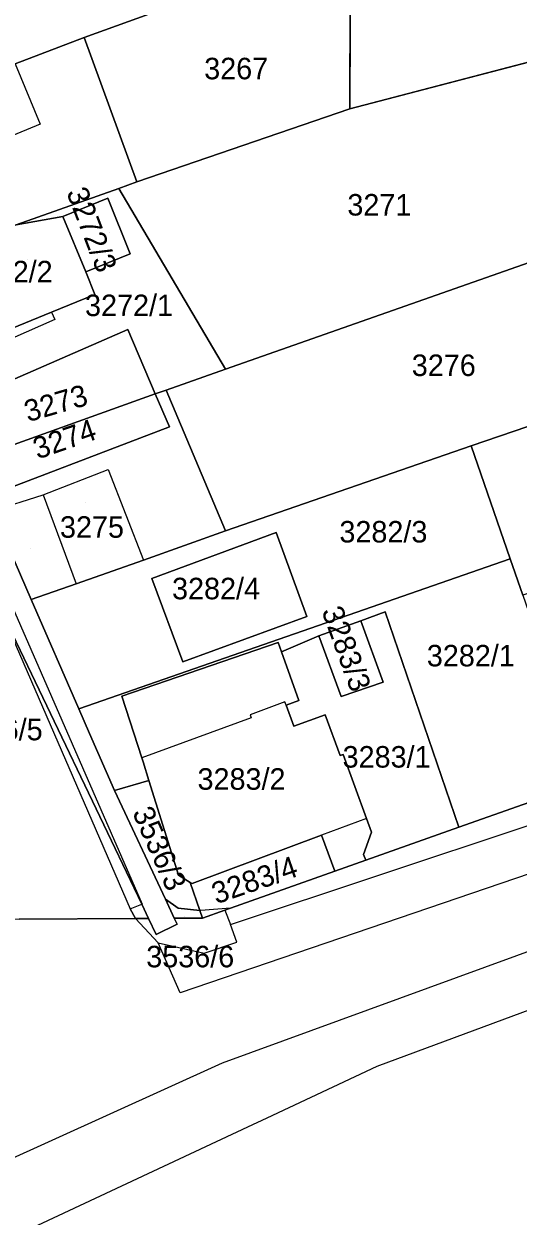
# Model space of a CAD drawing. Extents: x -262657 to -261595, y -1238015 to -1237156.
# Drawn here: x -261855.5 to -261809.5, y -1237959.1 to -1237848.2 of the extents above; entities that cross this region are included whole.
import ezdxf

# ---------------------------------------------------------------- set-up
doc = ezdxf.new("R2010")
doc.units = 0
for name, color, linetype in [('body_kn', 7, 'Continuous'), ('kladpar_druhypozemkov', 7, 'Continuous'), ('kladpar_hranice', 7, 'Continuous'), ('kladpar_parcelnecisla', 7, 'Continuous'), ('kladpar_plochy', 7, 'Continuous'), ('kladpar_sipky', 7, 'Continuous'), ('zappar_hrandruhpozemk', 7, 'Continuous')]:
    doc.layers.add(name, color=color, linetype=linetype)

msp = doc.modelspace()

# ---------------------------------------------------------------- linework, layer by layer
at = {"layer": 'body_kn'}
for p, q in [((-261849.86, -1237849.49), (-261849.86, -1237849.49)), ((-261825.16, -1237856.15), (-261825.16, -1237856.15)), ((-261825.16, -1237856.15), (-261825.16, -1237856.15)), ((-261853.94, -1237857.55), (-261853.94, -1237857.55)), ((-261844.94, -1237862.93), (-261844.94, -1237862.93)), ((-261846.62, -1237863.53), (-261846.62, -1237863.53)), ((-261847.66, -1237864.45), (-261847.66, -1237864.45)), ((-261851.85, -1237866.15), (-261851.85, -1237866.15)), ((-261851.85, -1237866.15), (-261851.85, -1237866.15)), ((-261845.57, -1237869.61), (-261845.57, -1237869.61)), ((-261849.71, -1237871.29), (-261849.71, -1237871.29)), ((-261849.71, -1237871.29), (-261849.71, -1237871.29)), ((-261848.86, -1237873.39), (-261848.86, -1237873.39)), ((-261852.89, -1237875.03), (-261852.89, -1237875.03)), ((-261852.89, -1237875.03), (-261852.89, -1237875.03)), ((-261852.58, -1237875.73), (-261852.58, -1237875.73)), ((-261845.79, -1237876.67), (-261845.79, -1237876.67)), ((-261836.71, -1237880.35), (-261836.71, -1237880.35)), ((-261836.71, -1237880.35), (-261836.71, -1237880.35)), ((-261843.24, -1237882.64), (-261843.24, -1237882.64)), ((-261843.24, -1237882.64), (-261843.24, -1237882.64)), ((-261842.22, -1237882.31), (-261842.22, -1237882.31)), ((-261842.22, -1237882.31), (-261842.22, -1237882.31)), ((-261841.92, -1237885.7), (-261841.92, -1237885.7)), ((-261813.88, -1237887.48), (-261813.88, -1237887.48)), ((-261847.61, -1237889.67), (-261847.61, -1237889.67)), ((-261853.65, -1237892.02), (-261853.65, -1237892.02)), ((-261853.65, -1237892.02), (-261853.65, -1237892.02)), ((-261836.71, -1237895.38), (-261836.71, -1237895.38)), ((-261831.99, -1237895.54), (-261831.99, -1237895.54)), ((-261844.34, -1237898.1), (-261844.34, -1237898.1)), ((-261810.24, -1237897.97), (-261810.24, -1237897.97)), ((-261850.59, -1237900.3), (-261850.59, -1237900.3)), ((-261843.57, -1237899.8), (-261843.57, -1237899.8)), ((-261843.57, -1237899.8), (-261843.57, -1237899.8)), ((-261854.78, -1237901.75), (-261854.78, -1237901.75)), ((-261854.78, -1237901.75), (-261854.78, -1237901.75)), ((-261829.14, -1237903.34), (-261829.14, -1237903.34)), ((-261824.12, -1237903.73), (-261824.12, -1237903.73)), ((-261821.85, -1237902.91), (-261821.85, -1237902.91)), ((-261831.81, -1237905.77), (-261831.81, -1237905.77)), ((-261828.03, -1237905.14), (-261828.03, -1237905.14)), ((-261828.03, -1237905.14), (-261828.03, -1237905.14)), ((-261831.51, -1237906.62), (-261831.51, -1237906.62)), ((-261840.69, -1237907.57), (-261840.69, -1237907.57)), ((-261822.05, -1237909.45), (-261822.05, -1237909.45)), ((-261846.35, -1237910.75), (-261846.35, -1237910.75)), ((-261831.18, -1237911.28), (-261831.18, -1237911.28)), ((-261831.06, -1237911.6), (-261831.06, -1237911.6)), ((-261831.06, -1237911.6), (-261831.06, -1237911.6)), ((-261829.89, -1237911.14), (-261829.89, -1237911.14)), ((-261825.96, -1237910.79), (-261825.96, -1237910.79)), ((-261850.36, -1237911.93), (-261850.36, -1237911.93)), ((-261850.36, -1237911.93), (-261850.36, -1237911.93)), ((-261834.41, -1237912.47), (-261834.41, -1237912.47)), ((-261834.31, -1237912.75), (-261834.31, -1237912.75)), ((-261827.43, -1237912.48), (-261827.43, -1237912.48)), ((-261830.35, -1237913.55), (-261830.35, -1237913.55)), ((-261849.36, -1237914.23), (-261849.36, -1237914.23)), ((-261825.78, -1237916.17), (-261825.78, -1237916.17)), ((-261844.49, -1237916.47), (-261844.49, -1237916.47)), ((-261844.37, -1237916.85), (-261844.37, -1237916.85)), ((-261826.04, -1237916.27), (-261826.04, -1237916.27)), ((-261843.84, -1237918.59), (-261843.84, -1237918.59)), ((-261847.03, -1237919.51), (-261847.03, -1237919.51)), ((-261847.03, -1237919.51), (-261847.03, -1237919.51)), ((-261823.6, -1237922.13), (-261823.6, -1237922.13)), ((-261823.6, -1237922.13), (-261823.6, -1237922.13)), ((-261827.77, -1237923.68), (-261827.77, -1237923.68)), ((-261823.13, -1237923.4), (-261823.13, -1237923.4)), ((-261815.02, -1237922.93), (-261815.02, -1237922.93)), ((-261815.02, -1237922.93), (-261815.02, -1237922.93)), ((-261823.87, -1237925.46), (-261823.87, -1237925.46)), ((-261823.67, -1237926.01), (-261823.67, -1237926.01)), ((-261826.55, -1237927.03), (-261826.55, -1237927.03)), ((-261841.07, -1237927.4), (-261841.07, -1237927.4)), ((-261839.99, -1237928.06), (-261839.99, -1237928.06)), ((-261839.99, -1237928.06), (-261839.99, -1237928.06)), ((-261839.82, -1237928.16), (-261839.82, -1237928.16)), ((-261839.82, -1237928.16), (-261839.82, -1237928.16)), ((-261845.58, -1237930.53), (-261845.58, -1237930.53)), ((-261845.58, -1237930.53), (-261845.58, -1237930.53)), ((-261844.5, -1237930.1), (-261844.5, -1237930.1)), ((-261844.45, -1237930.08), (-261844.45, -1237930.08)), ((-261842.3, -1237929.61), (-261842.3, -1237929.61)), ((-261841.11, -1237930.46), (-261841.11, -1237930.46)), ((-261836.23, -1237930.47), (-261836.23, -1237930.47)), ((-261836.23, -1237930.47), (-261836.23, -1237930.47)), ((-261845.09, -1237931.42), (-261845.09, -1237931.42)), ((-261845.09, -1237931.42), (-261845.09, -1237931.42)), ((-261843.87, -1237931.41), (-261843.87, -1237931.41)), ((-261843.87, -1237931.41), (-261843.87, -1237931.41)), ((-261841.47, -1237931.4), (-261841.47, -1237931.4)), ((-261839.1, -1237930.68), (-261839.1, -1237930.68)), ((-261838.99, -1237930.69), (-261838.99, -1237930.69)), ((-261838.86, -1237931.38), (-261838.86, -1237931.38)), ((-261838.86, -1237931.38), (-261838.86, -1237931.38)), ((-261836.77, -1237930.66), (-261836.77, -1237930.66)), ((-261836.77, -1237930.66), (-261836.77, -1237930.66)), ((-261841.21, -1237931.96), (-261841.21, -1237931.96)), ((-261836.26, -1237931.97), (-261836.26, -1237931.97)), ((-261843.16, -1237932.9), (-261843.16, -1237932.9)), ((-261842.98, -1237933.69), (-261842.98, -1237933.69)), ((-261835.66, -1237933.61), (-261835.66, -1237933.61)), ((-261838.69, -1237934.64), (-261838.69, -1237934.64)), ((-261840.93, -1237938.33), (-261840.93, -1237938.33)), ((-261837.01, -1237944.88), (-261837.01, -1237944.88)), ((-261822.63, -1237945.17), (-261822.63, -1237945.17)), ((-261832.88, -1237949.98), (-261832.88, -1237949.98)), ((-261834.67, -1237950.82), (-261834.67, -1237950.82))]:
    msp.add_line(p, q, dxfattribs=at)
at = {"layer": 'kladpar_druhypozemkov'}
for p, q in [((-261834.97, -1237851.22), (-261834.97, -1237851.22)), ((-261822.49, -1237864.62), (-261822.49, -1237864.62)), ((-261847.47, -1237867.59), (-261847.47, -1237867.59)), ((-261855.11, -1237870.19), (-261855.11, -1237870.19)), ((-261845.66, -1237873.13), (-261845.66, -1237873.13)), ((-261816.3, -1237879.35), (-261816.3, -1237879.35)), ((-261852.61, -1237882.96), (-261852.61, -1237882.96)), ((-261849.73, -1237892.77), (-261849.73, -1237892.77)), ((-261820.38, -1237894.4), (-261820.38, -1237894.4)), ((-261854.83, -1237897), (-261854.83, -1237897)), ((-261836.81, -1237899.83), (-261836.81, -1237899.83)), ((-261813.56, -1237905.81), (-261813.56, -1237905.81)), ((-261824.17, -1237906.62), (-261824.17, -1237906.62)), ((-261821.75, -1237915.81), (-261821.75, -1237915.81)), ((-261834.44, -1237917.08), (-261834.44, -1237917.08)), ((-261844.63, -1237922.49), (-261844.63, -1237922.49)), ((-261833.44, -1237927.17), (-261833.44, -1237927.17)), ((-261840.51, -1237931.2), (-261840.51, -1237931.2))]:
    msp.add_line(p, q, dxfattribs=at)
at = {"layer": 'kladpar_hranice'}
for points in [[(-261755.63, -1237818.43), (-261750.68, -1237833.95), (-261752.22, -1237834.48), (-261760.3, -1237837.27), (-261775.64, -1237842.43), (-261804.23, -1237852.16), (-261804.96, -1237850.86), (-261825.16, -1237856.15), (-261825.08, -1237840.58), (-261809.58, -1237835.59), (-261789.12, -1237829.1), (-261755.63, -1237818.43)], [(-261831.04, -1237842.68), (-261849.86, -1237849.49), (-261856.26, -1237851.95), (-261858.52, -1237852.84), (-261861.86, -1237845.07), (-261854.25, -1237841.77), (-261855.9, -1237837.59), (-261854.94, -1237837.24), (-261836.33, -1237829.97), (-261831.04, -1237842.68)], [(-261831.04, -1237842.68), (-261825.08, -1237840.58), (-261825.16, -1237856.15), (-261844.94, -1237862.93), (-261849.86, -1237849.49), (-261831.04, -1237842.68)], [(-261867.67, -1237871.68), (-261873.52, -1237857.83), (-261858.52, -1237852.84), (-261856.26, -1237851.95), (-261849.86, -1237849.49), (-261844.94, -1237862.93), (-261846.62, -1237863.53), (-261856.17, -1237866.91), (-261862.97, -1237869.61), (-261867.67, -1237871.68)], [(-261825.16, -1237856.15), (-261804.96, -1237850.86), (-261804.23, -1237852.16), (-261798.67, -1237866.97), (-261836.71, -1237880.35), (-261846.62, -1237863.53), (-261844.94, -1237862.93), (-261825.16, -1237856.15)], [(-261836.71, -1237880.35), (-261842.22, -1237882.31), (-261843.24, -1237882.64), (-261845.79, -1237876.67), (-261862.42, -1237883.92), (-261863.85, -1237880.67), (-261864.24, -1237879.6), (-261867.67, -1237871.68), (-261862.97, -1237869.61), (-261859.78, -1237877.5), (-261859.66, -1237877.79), (-261852.89, -1237875.03), (-261848.86, -1237873.39), (-261849.71, -1237871.29), (-261845.57, -1237869.61), (-261847.66, -1237864.45), (-261851.85, -1237866.15), (-261856.17, -1237866.91), (-261846.62, -1237863.53), (-261836.71, -1237880.35)], [(-261849.71, -1237871.29), (-261851.85, -1237866.15), (-261847.66, -1237864.45), (-261845.57, -1237869.61), (-261849.71, -1237871.29)], [(-261851.85, -1237866.15), (-261849.71, -1237871.29), (-261848.86, -1237873.39), (-261852.89, -1237875.03), (-261859.66, -1237877.79), (-261859.78, -1237877.5), (-261862.97, -1237869.61), (-261856.17, -1237866.91), (-261851.85, -1237866.15)], [(-261794.07, -1237880.71), (-261813.88, -1237887.48), (-261836.71, -1237895.38), (-261842.22, -1237882.31), (-261836.71, -1237880.35), (-261798.67, -1237866.97), (-261794.07, -1237880.71)], [(-261843.24, -1237882.64), (-261860.37, -1237888.77), (-261862.42, -1237883.92), (-261845.79, -1237876.67), (-261843.24, -1237882.64)], [(-261794.07, -1237880.71), (-261789.26, -1237894.72), (-261794.77, -1237896.57), (-261809.06, -1237901.36), (-261810.24, -1237897.97), (-261813.88, -1237887.48), (-261794.07, -1237880.71)], [(-261843.24, -1237882.64), (-261841.92, -1237885.7), (-261858.89, -1237892.19), (-261860.37, -1237888.77), (-261843.24, -1237882.64)], [(-261842.22, -1237882.31), (-261836.71, -1237895.38), (-261844.34, -1237898.1), (-261850.59, -1237900.3), (-261854.78, -1237901.75), (-261858.36, -1237893.51), (-261858.89, -1237892.19), (-261841.92, -1237885.7), (-261843.24, -1237882.64), (-261842.22, -1237882.31)], [(-261854.78, -1237901.75), (-261850.59, -1237900.3), (-261844.34, -1237898.1), (-261836.71, -1237895.38), (-261813.88, -1237887.48), (-261810.24, -1237897.97)], [(-261858.36, -1237893.51), (-261854.78, -1237901.75), (-261850.36, -1237911.93), (-261849.36, -1237914.23), (-261847.03, -1237919.51), (-261842.3, -1237929.61), (-261841.47, -1237931.4), (-261841.21, -1237931.96), (-261843.16, -1237932.9), (-261843.87, -1237931.41)], [(-261855.91, -1237931.48), (-261845.09, -1237931.42), (-261843.87, -1237931.41), (-261843.16, -1237932.9), (-261841.21, -1237931.96), (-261841.47, -1237931.4), (-261838.86, -1237931.38), (-261836.77, -1237930.66), (-261836.23, -1237930.47), (-261826.55, -1237927.03), (-261823.67, -1237926.01), (-261815.02, -1237922.93), (-261803.05, -1237918.72), (-261799.45, -1237917.56), (-261788.79, -1237913.99), (-261779.37, -1237910.9), (-261774.74, -1237909.35), (-261760.66, -1237904.62), (-261755.07, -1237902.82), (-261753.55, -1237902.35), (-261746.14, -1237899.86), (-261733.49, -1237895.72)], [(-261843.57, -1237899.8), (-261831.99, -1237895.54), (-261829.14, -1237903.34), (-261840.69, -1237907.57), (-261843.57, -1237899.8)], [(-261829.14, -1237903.34), (-261831.99, -1237895.54), (-261843.57, -1237899.8), (-261840.69, -1237907.57), (-261829.14, -1237903.34)], [(-261810.24, -1237897.97), (-261850.36, -1237911.93), (-261854.78, -1237901.75)], [(-261850.36, -1237911.93), (-261810.24, -1237897.97), (-261809.06, -1237901.36), (-261803.05, -1237918.72), (-261815.02, -1237922.93), (-261821.85, -1237902.91), (-261824.12, -1237903.73), (-261828.03, -1237905.14), (-261831.51, -1237906.62), (-261831.81, -1237905.77), (-261846.35, -1237910.75), (-261844.49, -1237916.47), (-261844.37, -1237916.85), (-261843.84, -1237918.59), (-261847.03, -1237919.51), (-261849.36, -1237914.23), (-261850.36, -1237911.93)], [(-261867.89, -1237908.17), (-261866.13, -1237907.4), (-261864.96, -1237906.9), (-261860.38, -1237904.91), (-261857.29, -1237903.53), (-261857.22, -1237903.5), (-261844.5, -1237930.1), (-261843.87, -1237931.41)], [(-261843.87, -1237931.41), (-261844.5, -1237930.1), (-261857.22, -1237903.5), (-261857.29, -1237903.53), (-261860.38, -1237904.91), (-261864.96, -1237906.9), (-261866.13, -1237907.4), (-261867.89, -1237908.17)], [(-261815.02, -1237922.93), (-261823.67, -1237926.01), (-261823.87, -1237925.46), (-261823.13, -1237923.4), (-261823.6, -1237922.13), (-261825.78, -1237916.17), (-261826.04, -1237916.27), (-261827.43, -1237912.48), (-261830.35, -1237913.55), (-261831.06, -1237911.6), (-261829.89, -1237911.14), (-261831.51, -1237906.62), (-261828.03, -1237905.14), (-261825.96, -1237910.79), (-261822.05, -1237909.45), (-261824.12, -1237903.73), (-261821.85, -1237902.91), (-261815.02, -1237922.93)], [(-261828.03, -1237905.14), (-261824.12, -1237903.73), (-261822.05, -1237909.45), (-261825.96, -1237910.79), (-261828.03, -1237905.14)], [(-261839.82, -1237928.16), (-261839.99, -1237928.06), (-261841.07, -1237927.4), (-261843.84, -1237918.59), (-261844.37, -1237916.85), (-261844.49, -1237916.47), (-261846.35, -1237910.75), (-261831.81, -1237905.77), (-261831.51, -1237906.62), (-261829.89, -1237911.14), (-261831.06, -1237911.6), (-261830.35, -1237913.55), (-261827.43, -1237912.48), (-261826.04, -1237916.27), (-261825.78, -1237916.17), (-261823.6, -1237922.13), (-261823.13, -1237923.4), (-261823.87, -1237925.46), (-261823.67, -1237926.01), (-261826.55, -1237927.03), (-261827.77, -1237923.68), (-261839.82, -1237928.16)], [(-261727.99, -1237912.57), (-261763.54, -1237924.41), (-261786.15, -1237931.76), (-261793.04, -1237934.21), (-261822.63, -1237945.17), (-261832.88, -1237949.98), (-261834.67, -1237950.82), (-261857.62, -1237961.58), (-261876.1, -1237970.13), (-261879.42, -1237971.62), (-261885.86, -1237974.51), (-261889.63, -1237976.21), (-261941.87, -1237999.81), (-261949.48, -1238002.8), (-261968.18, -1238010.15), (-261970.85, -1238012.16), (-261972.53, -1238015.11), (-261973.89, -1238014.34), (-261981.54, -1238009.7), (-261992.4, -1238009.93), (-261991.11, -1238000.48), (-261996, -1238000.09), (-261995.78, -1237991.95), (-261995.49, -1237985.74)], [(-261847.03, -1237919.51), (-261843.84, -1237918.59), (-261841.07, -1237927.4), (-261839.99, -1237928.06), (-261839.1, -1237930.68), (-261841.11, -1237930.46), (-261842.3, -1237929.61), (-261847.03, -1237919.51)], [(-261839.99, -1237928.06), (-261839.82, -1237928.16), (-261827.77, -1237923.68), (-261826.55, -1237927.03), (-261836.23, -1237930.47), (-261836.77, -1237930.66), (-261838.86, -1237931.38), (-261839.1, -1237930.68), (-261839.99, -1237928.06)], [(-261843.87, -1237931.41), (-261845.09, -1237931.42), (-261855.91, -1237931.48), (-261858.38, -1237931.51), (-261859.54, -1237928.73)], [(-261838.86, -1237931.38), (-261841.47, -1237931.4), (-261842.3, -1237929.61), (-261841.11, -1237930.46), (-261839.1, -1237930.68), (-261838.86, -1237931.38)]]:
    msp.add_lwpolyline(points, dxfattribs=at)
at = {"layer": 'kladpar_plochy'}
for p, q in [((-261825.16, -1237856.15), (-261825.08, -1237840.58)), ((-261804.96, -1237850.86), (-261825.16, -1237856.15)), ((-261836.71, -1237895.38), (-261813.88, -1237887.48)), ((-261813.88, -1237887.48), (-261810.24, -1237897.97)), ((-261844.34, -1237898.1), (-261836.71, -1237895.38)), ((-261831.99, -1237895.54), (-261843.57, -1237899.8)), ((-261829.14, -1237903.34), (-261831.99, -1237895.54)), ((-261850.59, -1237900.3), (-261844.34, -1237898.1)), ((-261810.24, -1237897.97), (-261850.36, -1237911.93)), ((-261854.78, -1237901.75), (-261850.59, -1237900.3)), ((-261843.57, -1237899.8), (-261840.69, -1237907.57)), ((-261850.36, -1237911.93), (-261854.78, -1237901.75)), ((-261840.69, -1237907.57), (-261829.14, -1237903.34))]:
    msp.add_line(p, q, dxfattribs=at)
for points in [[(-261831.04, -1237842.68), (-261849.86, -1237849.49), (-261856.26, -1237851.95), (-261858.52, -1237852.84), (-261861.86, -1237845.07), (-261854.25, -1237841.77), (-261855.9, -1237837.59), (-261854.94, -1237837.24), (-261836.33, -1237829.97)], [(-261831.04, -1237842.68), (-261825.08, -1237840.58), (-261825.16, -1237856.15), (-261844.94, -1237862.93), (-261849.86, -1237849.49)], [(-261867.67, -1237871.68), (-261873.52, -1237857.83), (-261858.52, -1237852.84), (-261856.26, -1237851.95), (-261849.86, -1237849.49), (-261844.94, -1237862.93), (-261846.62, -1237863.53), (-261856.17, -1237866.91), (-261862.97, -1237869.61)], [(-261825.16, -1237856.15), (-261804.96, -1237850.86), (-261804.23, -1237852.16), (-261798.67, -1237866.97), (-261836.71, -1237880.35), (-261846.62, -1237863.53), (-261844.94, -1237862.93)], [(-261836.71, -1237880.35), (-261842.22, -1237882.31), (-261843.24, -1237882.64), (-261845.79, -1237876.67), (-261862.42, -1237883.92), (-261863.85, -1237880.67), (-261864.24, -1237879.6), (-261867.67, -1237871.68), (-261862.97, -1237869.61), (-261859.78, -1237877.5), (-261859.66, -1237877.79), (-261852.89, -1237875.03), (-261848.86, -1237873.39), (-261849.71, -1237871.29), (-261845.57, -1237869.61), (-261847.66, -1237864.45), (-261851.85, -1237866.15), (-261856.17, -1237866.91), (-261846.62, -1237863.53)], [(-261849.71, -1237871.29), (-261851.85, -1237866.15), (-261847.66, -1237864.45), (-261845.57, -1237869.61)], [(-261851.85, -1237866.15), (-261849.71, -1237871.29), (-261848.86, -1237873.39), (-261852.89, -1237875.03), (-261859.66, -1237877.79), (-261859.78, -1237877.5), (-261862.97, -1237869.61), (-261856.17, -1237866.91)], [(-261794.07, -1237880.71), (-261813.88, -1237887.48), (-261836.71, -1237895.38), (-261842.22, -1237882.31), (-261836.71, -1237880.35), (-261798.67, -1237866.97)], [(-261843.24, -1237882.64), (-261860.37, -1237888.77), (-261862.42, -1237883.92), (-261845.79, -1237876.67)], [(-261794.07, -1237880.71), (-261789.26, -1237894.72), (-261794.77, -1237896.57), (-261809.06, -1237901.36), (-261810.24, -1237897.97), (-261813.88, -1237887.48)], [(-261843.24, -1237882.64), (-261841.92, -1237885.7), (-261858.89, -1237892.19), (-261860.37, -1237888.77)], [(-261842.22, -1237882.31), (-261836.71, -1237895.38), (-261844.34, -1237898.1), (-261850.59, -1237900.3), (-261854.78, -1237901.75), (-261858.36, -1237893.51), (-261858.89, -1237892.19), (-261841.92, -1237885.7), (-261843.24, -1237882.64)], [(-261843.57, -1237899.8), (-261831.99, -1237895.54), (-261829.14, -1237903.34), (-261840.69, -1237907.57)], [(-261850.36, -1237911.93), (-261810.24, -1237897.97), (-261809.06, -1237901.36), (-261803.05, -1237918.72), (-261815.02, -1237922.93), (-261821.85, -1237902.91), (-261824.12, -1237903.73), (-261828.03, -1237905.14), (-261831.51, -1237906.62), (-261831.81, -1237905.77), (-261846.35, -1237910.75), (-261844.49, -1237916.47), (-261844.37, -1237916.85), (-261843.84, -1237918.59), (-261847.03, -1237919.51), (-261849.36, -1237914.23)], [(-261859.54, -1237928.73), (-261861.24, -1237924.09), (-261863.34, -1237919.13), (-261867.89, -1237908.17), (-261866.13, -1237907.4), (-261864.96, -1237906.9), (-261860.38, -1237904.91), (-261857.29, -1237903.53), (-261857.22, -1237903.5), (-261844.5, -1237930.1), (-261843.87, -1237931.41), (-261845.09, -1237931.42), (-261855.91, -1237931.48), (-261858.38, -1237931.51)], [(-261815.02, -1237922.93), (-261823.67, -1237926.01), (-261823.87, -1237925.46), (-261823.13, -1237923.4), (-261823.6, -1237922.13), (-261825.78, -1237916.17), (-261826.04, -1237916.27), (-261827.43, -1237912.48), (-261830.35, -1237913.55), (-261831.06, -1237911.6), (-261829.89, -1237911.14), (-261831.51, -1237906.62), (-261828.03, -1237905.14), (-261825.96, -1237910.79), (-261822.05, -1237909.45), (-261824.12, -1237903.73), (-261821.85, -1237902.91)], [(-261828.03, -1237905.14), (-261824.12, -1237903.73), (-261822.05, -1237909.45), (-261825.96, -1237910.79)], [(-261839.82, -1237928.16), (-261839.99, -1237928.06), (-261841.07, -1237927.4), (-261843.84, -1237918.59), (-261844.37, -1237916.85), (-261844.49, -1237916.47), (-261846.35, -1237910.75), (-261831.81, -1237905.77), (-261831.51, -1237906.62), (-261829.89, -1237911.14), (-261831.06, -1237911.6), (-261830.35, -1237913.55), (-261827.43, -1237912.48), (-261826.04, -1237916.27), (-261825.78, -1237916.17), (-261823.6, -1237922.13), (-261823.13, -1237923.4), (-261823.87, -1237925.46), (-261823.67, -1237926.01), (-261826.55, -1237927.03), (-261827.77, -1237923.68)], [(-261847.03, -1237919.51), (-261843.84, -1237918.59), (-261841.07, -1237927.4), (-261839.99, -1237928.06), (-261839.1, -1237930.68), (-261841.11, -1237930.46), (-261842.3, -1237929.61)], [(-261839.99, -1237928.06), (-261839.82, -1237928.16), (-261827.77, -1237923.68), (-261826.55, -1237927.03), (-261836.23, -1237930.47), (-261836.77, -1237930.66), (-261838.86, -1237931.38), (-261839.1, -1237930.68)], [(-261838.86, -1237931.38), (-261841.47, -1237931.4), (-261842.3, -1237929.61), (-261841.11, -1237930.46), (-261839.1, -1237930.68)]]:
    msp.add_lwpolyline(points, close=True, dxfattribs=at)
for points in [[(-261858.36, -1237893.51), (-261854.78, -1237901.75), (-261850.36, -1237911.93), (-261849.36, -1237914.23), (-261847.03, -1237919.51), (-261842.3, -1237929.61), (-261841.47, -1237931.4), (-261841.21, -1237931.96), (-261843.16, -1237932.9), (-261843.87, -1237931.41), (-261844.5, -1237930.1), (-261857.22, -1237903.5)], [(-261855.91, -1237931.48), (-261845.09, -1237931.42), (-261843.87, -1237931.41), (-261843.16, -1237932.9), (-261841.21, -1237931.96), (-261841.47, -1237931.4), (-261838.86, -1237931.38), (-261836.77, -1237930.66), (-261836.23, -1237930.47), (-261826.55, -1237927.03), (-261823.67, -1237926.01), (-261815.02, -1237922.93), (-261803.05, -1237918.72), (-261799.45, -1237917.56), (-261788.79, -1237913.99), (-261779.37, -1237910.9), (-261774.74, -1237909.35), (-261760.66, -1237904.62), (-261755.07, -1237902.82), (-261753.55, -1237902.35), (-261746.14, -1237899.86), (-261733.49, -1237895.72)], [(-261727.99, -1237912.57), (-261763.54, -1237924.41), (-261786.15, -1237931.76), (-261793.04, -1237934.21), (-261822.63, -1237945.17), (-261832.88, -1237949.98), (-261834.67, -1237950.82), (-261857.62, -1237961.58)]]:
    msp.add_lwpolyline(points, dxfattribs=at)
at = {"layer": 'kladpar_sipky'}
msp.add_line((-261840.66, -1237931.34), (-261840.66, -1237931.34), dxfattribs=at)
at = {"layer": 'zappar_hrandruhpozemk'}
for p, q in [((-261853.94, -1237857.55), (-261860.27, -1237860.19)), ((-261852.89, -1237875.03), (-261852.58, -1237875.73)), ((-261852.58, -1237875.73), (-261863.85, -1237880.67)), ((-261847.61, -1237889.67), (-261844.34, -1237898.1)), ((-261853.65, -1237892.02), (-261850.59, -1237900.3)), ((-261857.29, -1237903.53), (-261845.58, -1237930.53)), ((-261834.31, -1237912.75), (-261844.49, -1237916.47)), ((-261773.83, -1237915.47), (-261840.93, -1237938.33)), ((-261823.6, -1237922.13), (-261827.77, -1237923.68)), ((-261845.58, -1237930.53), (-261844.5, -1237930.1)), ((-261845.09, -1237931.42), (-261845.58, -1237930.53)), ((-261836.23, -1237930.47), (-261838.99, -1237930.69)), ((-261795.73, -1237929.79), (-261837.01, -1237944.88)), ((-261838.99, -1237930.69), (-261839.1, -1237930.68)), ((-261836.77, -1237930.66), (-261836.26, -1237931.97)), ((-261840.93, -1237938.33), (-261842.98, -1237933.69)), ((-261838.69, -1237934.64), (-261835.66, -1237933.61)), ((-261838.69, -1237934.64), (-261835.66, -1237933.61)), ((-261837.01, -1237944.88), (-261867.58, -1237958.71))]:
    msp.add_line(p, q, dxfattribs=at)
for points in [[(-261866.72, -1237856.24), (-261856.26, -1237851.95), (-261853.94, -1237857.55)], [(-261870.74, -1237869.97), (-261844.45, -1237930.08), (-261844.5, -1237930.1)], [(-261858.36, -1237893.51), (-261853.65, -1237892.02), (-261847.61, -1237889.67)], [(-261831.06, -1237911.6), (-261831.18, -1237911.28), (-261834.41, -1237912.47), (-261834.31, -1237912.75)], [(-261835.66, -1237933.61), (-261836.26, -1237931.97), (-261794.68, -1237918.16)], [(-261835.66, -1237933.61), (-261836.26, -1237931.97), (-261794.68, -1237918.16)], [(-261845.58, -1237930.53), (-261845.09, -1237931.42), (-261842.98, -1237933.69), (-261838.69, -1237934.64)], [(-261845.09, -1237931.42), (-261842.98, -1237933.69), (-261838.69, -1237934.64)]]:
    msp.add_lwpolyline(points, dxfattribs=at)

# ---------------------------------------------------------------- texts
at = {"layer": 'kladpar_parcelnecisla'}
for s, p in [('3267', (-261838.69, -1237853.39)), ('3271', (-261825.38, -1237866.06)), ('3272/2', (-261860.96, -1237872.27)), ('3272/1', (-261849.77, -1237875.41)), ('3276', (-261819.39, -1237880.98)), ('3275', (-261852.1, -1237896.02)), ('3282/3', (-261826.12, -1237896.46)), ('3282/4', (-261841.68, -1237901.74)), ('3282/1', (-261817.99, -1237907.98)), ('3536/5', (-261861.89, -1237914.85)), ('3283/1', (-261825.82, -1237917.39)), ('3283/2', (-261839.31, -1237919.45)), ('3536/6', (-261844.08, -1237935.96))]:
    msp.add_text(s, height=2, dxfattribs=at).set_placement(p)
for s, rotation, p in [('3272/3', 291, (-261851.53, -1237863.89)), ('3273', 16, (-261855.08, -1237885.28)), ('3274', 19, (-261854.18, -1237888.75)), ('3283/3', 290, (-261827.8, -1237902.82)), ('3536/3', 294, (-261845.41, -1237921.56)), ('3283/4', 19, (-261837.57, -1237930.11))]:
    msp.add_text(s, height=2, rotation=rotation, dxfattribs=at).set_placement(p)

doc.saveas('drawing.dxf')
